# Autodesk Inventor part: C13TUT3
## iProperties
Shininess: 64.0
Length Units: 11269
Angle Units: 11279
Time Units: 11290
Mass Units: 11283
Length Display Precision: 3
Angle Display Precision: 2
Compacted: True
Part Number: C13TUT3
Document SubType Name: Modeling
Created: 2003-11
Designer: Owner
Manufacturer: Standard
Standards Organization: Custom
Density: 0.0
Volumn: 0.0
Area: 0.0
PropertySet Name: Model Information
Control State: 0
Master: False
Checked Out: False
Author: Owner
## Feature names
1. Sweep1
